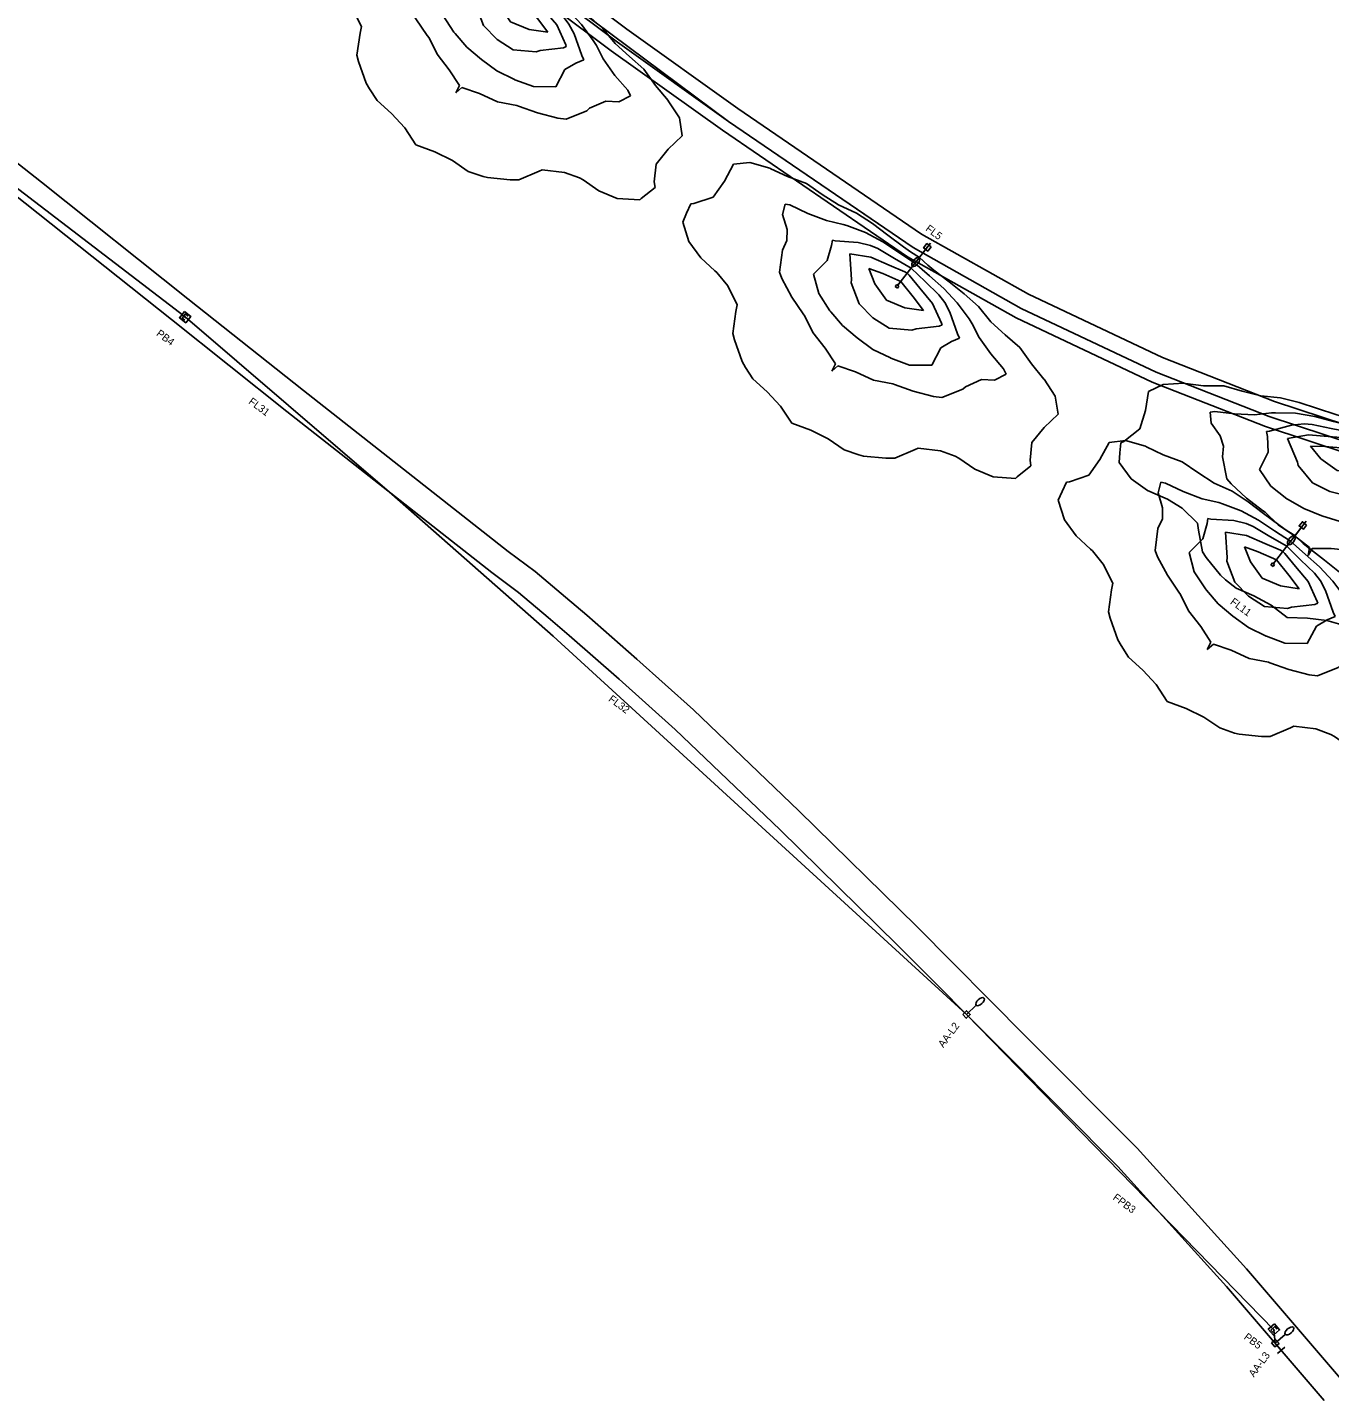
# Model space of a CAD drawing. Extents: x 1322666 to 1327584, y 458075 to 462260.
# Drawn here: x 1324242 to 1324730, y 460188 to 460702 of the extents above; entities that cross this region are included whole.
import ezdxf

# ---------------------------------------------------------------- set-up
doc = ezdxf.new("R2010")
doc.units = 0
for name, color, linetype in [('_CIVIL_CONSTRUCTION', 7, 'Continuous'), ('Default', 7, 'Continuous'), ('DR_P_Culvert', 7, 'Continuous'), ('DR_P_Culvert3D', 7, 'Continuous'), ('DR_X_Cells', 7, 'Continuous'), ('PF_X_Ground_Line', 7, 'Continuous'), ('UT_X_Cable_TV_FO', 7, 'Continuous'), ('UT_X_Misc_Cells', 7, 'Continuous'), ('UT_X_Oil', 7, 'Continuous')]:
    doc.layers.add(name, color=color, linetype=linetype)

# ---------------------------------------------------------------- blocks, each defined once
blk = doc.blocks.new('AGI32-IDj66arb-Project_1-LUMINAIRE-ERL2_19C330______Symbol')
at = {"layer": 'Default'}
for p, q in [((-0.03, 0), (0.03, 0)), ((0, 0.13), (0.24, 0.13)), ((0, -0.13), (0, 0.13)), ((0, 0.13), (0, 0.13)), ((0, 0.13), (0.24, 0.13)), ((0.24, 0.13), (0, 0.13)), ((0, -0.13), (0, 0.13)), ((0, 0.13), (0, 0.13)), ((0, 0.13), (0, -0.13)), ((0.24, 0.13), (0, 0.13)), ((0, 0.13), (0, -0.13)), ((0, -0.03), (0, 0.03)), ((0, 0.03), (0.03, 0)), ((0, -0.03), (0.03, 0)), ((0.24, 0.13), (0.24, -0.13)), ((0.24, 0.13), (0.24, 0.13)), ((0.24, 0.13), (0.24, 0.13)), ((0.24, 0.13), (0.24, -0.13)), ((0.24, -0.13), (0.24, 0.13)), ((0.24, -0.13), (0.24, 0.13)), ((0.24, -0.13), (0, -0.13)), ((0.24, -0.13), (0, -0.13)), ((0, -0.13), (0, -0.13)), ((0, -0.13), (0.24, -0.13)), ((0, -0.13), (0, -0.13)), ((0, -0.13), (0.24, -0.13)), ((0.24, -0.13), (0.24, -0.13)), ((0.24, -0.13), (0.24, -0.13))]:
    blk.add_line(p, q, dxfattribs=at)
blk = doc.blocks.new('AGI32-IDj66arb-Project_1-LUMINAIRE-ERL2_19C330______64-1')
at = {"layer": 'Default'}
blk.add_blockref('AGI32-IDj66arb-Project_1-LUMINAIRE-ERL2_19C330______Symbol', (0, 0), dxfattribs=at)
blk = doc.blocks.new('AGI32-IDj66arb-Project_1-LUMINAIRE-ERL2_19C330______Template1')
at = {"layer": 'Default'}
for p, q in [((9.14, 19.22), (10.58, 20.11)), ((10.58, 20.11), (10.97, 20.5)), ((10.97, 20.5), (12.6, 20.11)), ((12.6, 20.11), (12.8, 20.07)), ((12.8, 20.07), (13.99, 18.29)), ((3.66, 16.46), (4.29, 18.29)), ((4.29, 18.29), (5.49, 19.56)), ((5.49, 19.56), (7.31, 19.28)), ((7.31, 19.28), (9.14, 19.22)), ((13.99, 18.29), (14.48, 16.46)), ((3.25, 14.63), (3.66, 16.45)), ((3.66, 16.45), (3.66, 16.46)), ((14.48, 16.46), (14.57, 14.63)), ((2.69, 12.8), (3.25, 14.63)), ((14.57, 14.63), (14.63, 14.24)), ((5.23, 12.8), (5.49, 13.32)), ((5.49, 13.32), (6.62, 12.8)), ((14.63, 14.24), (15.08, 12.8)), ((2.59, 10.97), (2.69, 12.8)), ((4.85, 10.97), (5.23, 12.8)), ((6.62, 12.8), (7.31, 11.77)), ((7.31, 11.77), (8.8, 10.97)), ((15.08, 12.8), (16.17, 10.97)), ((2.44, 9.14), (2.59, 10.97)), ((4.29, 9.14), (4.85, 10.97)), ((8.8, 10.97), (9.14, 10.91)), ((9.14, 10.91), (10.97, 9.83)), ((16.17, 10.97), (16.46, 10.82)), ((16.46, 10.82), (18.29, 9.79)), ((2, 7.31), (2.44, 9.14)), ((3.66, 7.83), (4.29, 9.14)), ((10.97, 9.83), (11.39, 9.14)), ((11.39, 9.14), (12.17, 7.31)), ((18.29, 9.79), (18.8, 9.14)), ((18.8, 9.14), (19.94, 7.31)), ((1.89, 5.49), (2, 7.31)), ((2.95, 5.49), (3.47, 7.31)), ((3.47, 7.31), (3.66, 7.83)), ((4.09, 5.49), (5.27, 7.31)), ((5.27, 7.31), (5.49, 7.72)), ((5.49, 7.72), (6.19, 7.31)), ((6.19, 7.31), (7.31, 6.87)), ((7.31, 6.87), (9.14, 7.19)), ((9.14, 7.19), (10.42, 5.49)), ((12.17, 7.31), (12.76, 5.49)), ((19.94, 7.31), (20.11, 6.9)), ((20.11, 6.9), (20.59, 5.49)), ((1.86, 3.66), (1.89, 5.49)), ((2.64, 3.66), (2.95, 5.49)), ((3.66, 4.54), (4.09, 5.49)), ((4.43, 3.66), (5.39, 5.49)), ((5.39, 5.49), (5.49, 5.63)), ((5.49, 5.63), (5.75, 5.49)), ((5.75, 5.49), (7.31, 3.9)), ((10.42, 5.49), (10.97, 3.69)), ((12.76, 5.49), (12.8, 5.34)), ((12.8, 5.34), (13.64, 3.66)), ((20.59, 5.49), (20.69, 3.66)), ((3.42, 3.66), (3.66, 4.54)), ((1.85, 1.83), (1.86, 3.66)), ((2.53, 1.83), (2.64, 3.66)), ((3.22, 1.83), (3.42, 3.66)), ((4.03, 1.83), (4.43, 3.66)), ((5.05, 1.83), (5.49, 3.41)), ((5.49, 3.41), (6.36, 1.83)), ((7.31, 3.9), (7.65, 3.66)), ((7.65, 3.66), (8.83, 1.83)), ((10.97, 3.69), (10.98, 3.66)), ((10.98, 3.66), (11.36, 1.83)), ((13.64, 3.66), (14.06, 1.83)), ((20.69, 3.66), (21.05, 1.83)), ((1.83, 1.08), (1.85, 1.83)), ((2.41, 0), (2.53, 1.83)), ((3.01, 0), (3.22, 1.83)), ((3.66, 0.28), (4.03, 1.83)), ((4.62, 0), (5.05, 1.83)), ((6.36, 1.83), (6.85, 0)), ((8.83, 1.83), (8.98, 0)), ((11.36, 1.83), (11.4, 0)), ((14.06, 1.83), (14.63, 0.14)), ((21.05, 1.83), (21.63, 0)), ((1.73, 0), (1.83, 1.08)), ((3.62, 0), (3.66, 0.28)), ((14.63, 0.14), (15.4, 0)), ((1.83, -0.98), (1.73, 0)), ((1.85, -1.83), (1.83, -0.98)), ((2.55, -1.83), (2.41, 0)), ((3.25, -1.83), (3.01, 0)), ((3.66, -0.25), (3.62, 0)), ((4.07, -1.83), (3.66, -0.25)), ((5.07, -1.83), (4.62, 0)), ((6.85, 0), (6.29, -1.83)), ((8.98, 0), (8.72, -1.83)), ((11.4, 0), (11.31, -1.83)), ((14.63, -0.15), (14.04, -1.83)), ((15.4, 0), (14.63, -0.15)), ((21.63, 0), (20.99, -1.83)), ((1.88, -3.66), (1.85, -1.83)), ((2.67, -3.66), (2.55, -1.83)), ((3.47, -3.66), (3.25, -1.83)), ((4.53, -3.66), (4.07, -1.83)), ((5.49, -3.15), (5.07, -1.83)), ((6.29, -1.83), (5.49, -3.15)), ((8.72, -1.83), (7.6, -3.66)), ((11.31, -1.83), (10.97, -3.51)), ((14.04, -1.83), (13.56, -3.66)), ((20.99, -1.83), (20.7, -3.66)), ((1.89, -5.49), (1.88, -3.66)), ((2.97, -5.49), (2.67, -3.66)), ((3.66, -4.38), (3.47, -3.66)), ((5.49, -5.44), (4.53, -3.66)), ((7.31, -3.83), (5.49, -5.44)), ((7.6, -3.66), (7.31, -3.83)), ((10.94, -3.66), (10.29, -5.49)), ((10.97, -3.51), (10.94, -3.66)), ((13.56, -3.66), (12.8, -5.21)), ((20.7, -3.66), (20.55, -5.49)), ((4.15, -5.49), (3.66, -4.38)), ((12.8, -5.21), (12.73, -5.49)), ((2.03, -7.31), (1.89, -5.49)), ((3.54, -7.31), (2.97, -5.49)), ((5.37, -7.31), (4.15, -5.49)), ((10.29, -5.49), (9.14, -7.01)), ((12.73, -5.49), (12.12, -7.31)), ((20.55, -5.49), (20.11, -6.73)), ((2.46, -9.14), (2.03, -7.31)), ((3.66, -7.66), (3.54, -7.31)), ((4.35, -9.14), (3.66, -7.66)), ((5.49, -7.55), (5.37, -7.31)), ((5.91, -7.31), (5.49, -7.55)), ((7.31, -6.76), (5.91, -7.31)), ((9.14, -7.01), (7.31, -6.76)), ((12.12, -7.31), (11.3, -9.14)), ((19.86, -7.31), (18.68, -9.14)), ((20.11, -6.73), (19.86, -7.31)), ((2.61, -10.97), (2.46, -9.14)), ((4.89, -10.97), (4.35, -9.14)), ((10.97, -9.68), (9.14, -10.74)), ((11.3, -9.14), (10.97, -9.68)), ((18.29, -9.64), (16.46, -10.68)), ((18.68, -9.14), (18.29, -9.64)), ((2.71, -12.8), (2.61, -10.97)), ((5.29, -12.8), (4.89, -10.97)), ((7.31, -11.59), (6.44, -12.8)), ((8.15, -10.97), (7.31, -11.59)), ((9.14, -10.74), (8.15, -10.97)), ((15.87, -10.97), (14.99, -12.8)), ((16.46, -10.68), (15.87, -10.97)), ((3.3, -14.63), (2.71, -12.8)), ((5.49, -13.2), (5.29, -12.8)), ((6.44, -12.8), (5.49, -13.2)), ((14.99, -12.8), (14.63, -14.39)), ((3.66, -16.33), (3.3, -14.63)), ((14.6, -14.63), (14.44, -16.46)), ((14.63, -14.39), (14.6, -14.63)), ((3.68, -16.46), (3.66, -16.33)), ((4.41, -18.29), (3.68, -16.46)), ((14.44, -16.46), (13.9, -18.29)), ((5.49, -19.4), (4.41, -18.29)), ((7.31, -19.11), (5.49, -19.4)), ((9.14, -19.03), (7.31, -19.11)), ((10.75, -20.11), (9.14, -19.03)), ((13.9, -18.29), (12.8, -19.89)), ((10.97, -20.33), (10.75, -20.11)), ((11.9, -20.11), (10.97, -20.33)), ((12.8, -19.89), (11.9, -20.11))]:
    blk.add_line(p, q, dxfattribs=at)
blk = doc.blocks.new('AGI32-IDj66arb-Project_1-LUMINAIRE-ERL2_19C330______64')
at = {"layer": 'Default'}
for q in [(5.08, 0), (0, 0)]:
    blk.add_line((0, 0), q, dxfattribs=at)
for name, p in [('AGI32-IDj66arb-Project_1-LUMINAIRE-ERL2_19C330______Template1', (0, 0)), ('AGI32-IDj66arb-Project_1-LUMINAIRE-ERL2_19C330______64-1', (5.08, 0))]:
    blk.add_blockref(name, p, dxfattribs=at)

msp = doc.modelspace()

# ---------------------------------------------------------------- linework, layer by layer
at = {"layer": '_CIVIL_CONSTRUCTION'}
for p, q in [((1324593.91, 460332.38), (1324597.56, 460335.8)), ((1324709.56, 460209.31), (1324713.33, 460212.58))]:
    msp.add_line(p, q, dxfattribs=at)
for points in [[(1324592.5, 460332.42), (1324593.96, 460333.79), (1324595.33, 460332.34), (1324593.87, 460330.96)], [(1324708.15, 460209.41), (1324709.66, 460210.72), (1324710.97, 460209.21), (1324709.46, 460207.9)]]:
    msp.add_lwpolyline(points, close=True, dxfattribs=at)
for centre, major_axis in [((1324599.01, 460337.17), (1.46, 1.37)), ((1324714.85, 460213.89), (1.51, 1.31))]:
    msp.add_ellipse(centre, major_axis=major_axis, ratio=0.5, dxfattribs=at)
at = {"layer": 'DR_P_Culvert'}
for p, q in [((1324579.25, 460619.64), (1324576.17, 460615.7)), ((1324719.91, 460515.47), (1324716.83, 460511.53))]:
    msp.add_line(p, q, dxfattribs=at)
for points in [[(1324580.65, 460619.81), (1324579.42, 460618.24), (1324577.84, 460619.47), (1324579.08, 460621.05)], [(1324721.31, 460515.64), (1324720.08, 460514.06), (1324718.51, 460515.29), (1324719.74, 460516.87)]]:
    msp.add_lwpolyline(points, close=True, dxfattribs=at)
for centre in [(1324574.94, 460614.13), (1324715.6, 460509.95)]:
    msp.add_ellipse(centre, major_axis=(-1.23, -1.58), ratio=0.5, dxfattribs=at)
at = {"layer": 'DR_P_Culvert3D'}
for points in [[(1325313.61, 460381.67), (1325288.02, 460385.96), (1325265.6, 460390.72), (1325174.92, 460418.01), (1325091.91, 460443.61), (1324989.4, 460474.51), (1324895.32, 460503.04), (1324830.48, 460523.41), (1324771.61, 460541.39), (1324709.26, 460561.9), (1324667.39, 460578.33), (1324617.11, 460602.1), (1324577.13, 460624.61), (1324508.29, 460671.66), (1324466.72, 460701.28), (1324334.23, 460800.54), (1324181.37, 460915.08), (1323797.37, 461202.12), (1323665.93, 461300.42), (1323464.99, 461451.01), (1323298.56, 461579.22)], [(1325312.61, 460375.75), (1325286.9, 460380.06), (1325264.11, 460384.9), (1325173.17, 460412.27), (1325090.16, 460437.87), (1324987.66, 460468.76), (1324893.55, 460497.31), (1324828.71, 460517.68), (1324769.79, 460535.67), (1324707.22, 460556.25), (1324665.01, 460572.82), (1324614.35, 460596.77), (1324573.96, 460619.51), (1324504.85, 460666.74), (1324463.18, 460696.44), (1324330.63, 460795.74), (1324177.78, 460910.28), (1323793.78, 461197.32), (1323662.33, 461295.62), (1323461.36, 461446.23), (1323294.9, 461574.47)], [(1323292.45, 461571.3), (1323458.94, 461443.04), (1323659.93, 461292.42), (1323791.38, 461194.11), (1323928.66, 461091.5), (1324047.04, 461003.01), (1324175.38, 460907.08), (1324328.24, 460792.54), (1324460.82, 460693.21), (1324502.56, 460663.46), (1324571.84, 460616.11), (1324612.51, 460593.22), (1324663.42, 460569.15), (1324705.87, 460552.49), (1324768.59, 460531.86), (1324827.52, 460513.86), (1324892.37, 460493.49), (1324986.5, 460464.93), (1325088.99, 460434.04), (1325172, 460408.44), (1325263.12, 460381.03), (1325286.15, 460376.13), (1325311.95, 460371.8)], [(1323769.14, 461021), (1323830.68, 460971.15), (1323902.43, 460913.55), (1324025.79, 460817.22), (1324184.37, 460693.72), (1324247.58, 460644), (1324302.39, 460600.37), (1324345.59, 460566.06), (1324422.31, 460505.74), (1324432.36, 460498.2), (1324443.79, 460488.66), (1324451.71, 460481.87), (1324470.52, 460465.4), (1324491.64, 460446.42), (1324531.14, 460408.67), (1324575.16, 460365.41), (1324616.32, 460324.05), (1324657.82, 460282.32), (1324698.81, 460237.16), (1324735.51, 460194.32)], [(1324727.92, 460187.81), (1324691.31, 460230.54), (1324650.57, 460275.43), (1324609.23, 460317), (1324568.11, 460358.31), (1324524.18, 460401.49), (1324484.84, 460439.09), (1324463.88, 460457.92), (1324445.16, 460474.31), (1324437.33, 460481.03), (1324426.16, 460490.36), (1324416.22, 460497.81), (1324339.39, 460558.21), (1324296.16, 460592.55), (1324241.37, 460636.16), (1324178.21, 460685.84), (1324019.64, 460809.33), (1323896.22, 460905.71), (1323824.4, 460963.36), (1323762.85, 461013.23)]]:
    msp.add_lwpolyline(points, dxfattribs=at)
at = {"layer": 'DR_X_Cells'}
for p, q in [((1324300.84, 460593.88), (1324301.63, 460593.27)), ((1324708.7, 460214.85), (1324709.35, 460214.09))]:
    msp.add_line(p, q, dxfattribs=at)
for points in [[(1324301.03, 460595.62), (1324303.4, 460593.78), (1324301.56, 460591.41), (1324299.19, 460593.25)], [(1324709.23, 460216.51), (1324711.19, 460214.24), (1324708.92, 460212.28), (1324706.96, 460214.55)]]:
    msp.add_lwpolyline(points, close=True, dxfattribs=at)
for points in [[(1324302.44, 460593.9), (1324301.45, 460594.67), (1324300.23, 460593.09), (1324301.21, 460592.32)], [(1324710.27, 460214.55), (1324709.46, 460215.5), (1324707.94, 460214.19), (1324708.76, 460213.25)]]:
    msp.add_lwpolyline(points, dxfattribs=at)
at = {"layer": 'PF_X_Ground_Line'}
msp.add_line((1324709.07, 460214.32), (1324593.91, 460332.38), dxfattribs=at)
for points in [[(1324301.3, 460593.57), (1324019.64, 460809.33), (1323896.22, 460905.71), (1323781.75, 460997.82)], [(1325336.51, 460403.02), (1325289.49, 460388.85), (1325213.26, 460400.13), (1325090.16, 460437.87), (1324828.71, 460517.68), (1324769.79, 460535.67), (1324707.22, 460556.25), (1324665.01, 460572.82), (1324614.35, 460596.77), (1324573.96, 460619.51), (1324553.09, 460633.8), (1324504.85, 460666.74), (1324410.85, 460736.87)], [(1324593.91, 460332.38), (1324439.2, 460474.03), (1324378.67, 460527.17), (1324301.3, 460593.57)]]:
    msp.add_lwpolyline(points, dxfattribs=at)
at = {"layer": 'UT_X_Cable_TV_FO'}
msp.add_line((1324709.56, 460209.31), (1324709.07, 460214.35), dxfattribs=at)
at = {"layer": 'UT_X_Oil'}
for p, q in [((1324709.19, 460209.7), (1324711.79, 460206.64)), ((1324710.35, 460205.41), (1324713.11, 460207.76))]:
    msp.add_line(p, q, dxfattribs=at)

# ---------------------------------------------------------------- block references
at = {"layer": 'DR_P_Culvert'}
for p, xscale, yscale, rotation in [((1324439.68, 460725.48), 3.9370000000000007, 3.9370000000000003, -127.5957929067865), ((1324580.43, 460621.24), 3.9370000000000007, 3.9370000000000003, -127.5957929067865), ((1324741.4, 460561.62), 3.9370000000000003, 3.9369999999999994, -108.74000354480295), ((1324721.09, 460517.06), 3.9370000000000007, 3.9370000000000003, -127.5957929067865)]:
    msp.add_blockref('AGI32-IDj66arb-Project_1-LUMINAIRE-ERL2_19C330______64', p, dxfattribs=dict(at, xscale=xscale, yscale=yscale, rotation=rotation))

# ---------------------------------------------------------------- texts
at = {"layer": 'UT_X_Misc_Cells'}
for s, rotation, p in [('FL5', 323.4759, (1324578.34, 460626.07)), ('PB4', 323.4759, (1324290.3, 460586.82)), ('FL31', 323.4759, (1324324.82, 460561.34)), ('FL11', 323.4759, (1324692.46, 460486.35)), ('FL32', 323.4759, (1324459.61, 460449.94)), ('AA-L2', 53.4759, (1324585.26, 460319.74)), ('FPB3', 323.4759, (1324648.48, 460263.3)), ('PB5', 323.4759, (1324697.57, 460211.09)), ('AA-L3', 53.4759, (1324701.57, 460196.36))]:
    msp.add_text(s, height=2.8, rotation=rotation, dxfattribs=at).set_placement(p)

doc.saveas('drawing.dxf')
